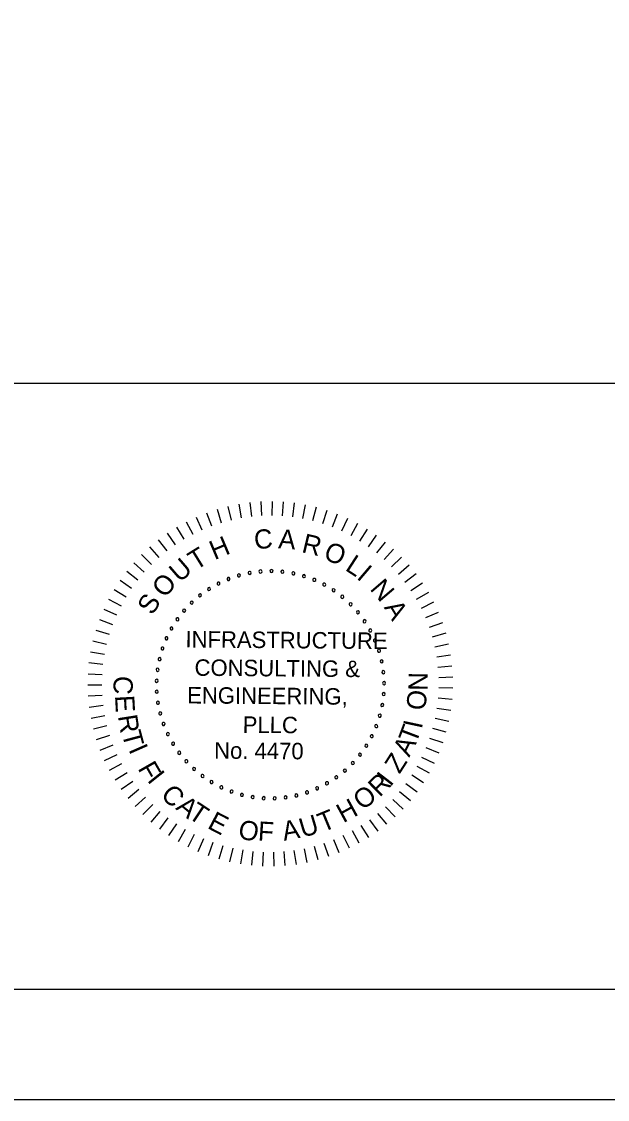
# Model space of a CAD drawing. Extents: x -305 to -161, y -187 to -99.
# Drawn here: x -204.36 to -193.73, y -187.49 to -167.93 of the extents above; entities that cross this region are included whole.
import ezdxf

# ---------------------------------------------------------------- set-up
doc = ezdxf.new("R2010")
doc.units = 0
for name, color, linetype in [('BR_BORDER LINES', 7, 'Continuous'), ('BR_TEXT', 7, 'Continuous'), ('Level 31', 7, 'Continuous')]:
    doc.layers.add(name, color=color, linetype=linetype)

msp = doc.modelspace()

# ---------------------------------------------------------------- linework, layer by layer
at = {"layer": 'BR_BORDER LINES'}
for p, q in [((-214.64, -174.489), (-193.18, -174.489)), ((-297.843, -185.489), (-163.178, -185.489))]:
    msp.add_line(p, q, dxfattribs=at)
at = {"layer": 'BR_TEXT'}
for p, q in [((-200.016, -176.64), (-200.002, -176.894)), ((-199.814, -176.636), (-199.816, -176.89)), ((-200.81, -176.779), (-200.735, -177.023)), ((-200.615, -176.726), (-200.555, -176.974)), ((-200.417, -176.685), (-200.373, -176.936)), ((-200.217, -176.656), (-200.188, -176.909)), ((-199.612, -176.644), (-199.63, -176.898)), ((-199.411, -176.664), (-199.444, -176.917)), ((-199.212, -176.697), (-199.26, -176.947)), ((-199.015, -176.741), (-199.079, -176.988)), ((-198.821, -176.798), (-198.9, -177.04)), ((-201.37, -177.007), (-201.252, -177.233)), ((-201.188, -176.92), (-201.084, -177.153)), ((-201.001, -176.844), (-200.912, -177.082)), ((-198.631, -176.866), (-198.724, -177.103)), ((-198.446, -176.946), (-198.553, -177.177)), ((-201.716, -177.215), (-201.572, -177.425)), ((-201.546, -177.106), (-201.415, -177.324)), ((-198.265, -177.037), (-198.387, -177.261)), ((-198.091, -177.139), (-198.226, -177.355)), ((-201.879, -177.334), (-201.723, -177.535)), ((-197.923, -177.251), (-198.071, -177.458)), ((-197.762, -177.373), (-197.922, -177.571)), ((-202.182, -177.601), (-202.002, -177.781)), ((-202.035, -177.463), (-201.866, -177.654)), ((-197.609, -177.505), (-197.781, -177.693)), ((-202.321, -177.748), (-202.13, -177.917)), ((-197.464, -177.646), (-197.647, -177.823)), ((-197.329, -177.795), (-197.522, -177.961)), ((-202.45, -177.903), (-202.25, -178.06)), ((-197.202, -177.952), (-197.405, -178.106)), ((-202.57, -178.065), (-202.36, -178.21)), ((-197.086, -178.117), (-197.298, -178.258)), ((-202.679, -178.235), (-202.461, -178.366)), ((-196.979, -178.289), (-197.199, -178.417)), ((-202.867, -178.593), (-202.634, -178.696)), ((-202.779, -178.411), (-202.553, -178.529)), ((-196.883, -178.467), (-197.111, -178.581)), ((-202.944, -178.779), (-202.705, -178.869)), ((-196.799, -178.65), (-197.033, -178.75)), ((-203.009, -178.97), (-202.766, -179.045)), ((-196.725, -178.838), (-196.965, -178.924)), ((-203.063, -179.165), (-202.815, -179.225)), ((-196.664, -179.03), (-196.908, -179.101)), ((-203.104, -179.363), (-202.853, -179.407)), ((-196.614, -179.226), (-196.862, -179.282)), ((-203.134, -179.562), (-202.881, -179.592)), ((-196.576, -179.424), (-196.827, -179.465)), ((-203.151, -179.764), (-202.897, -179.777)), ((-196.55, -179.625), (-196.804, -179.65)), ((-203.156, -179.965), (-202.901, -179.964)), ((-196.537, -179.826), (-196.791, -179.836)), ((-203.149, -180.167), (-202.895, -180.15)), ((-196.535, -180.028), (-196.79, -180.022)), ((-203.129, -180.368), (-202.877, -180.335)), ((-196.547, -180.23), (-196.8, -180.208)), ((-203.097, -180.568), (-202.847, -180.52)), ((-196.57, -180.43), (-196.822, -180.393)), ((-203.053, -180.765), (-202.807, -180.701)), ((-196.606, -180.629), (-196.855, -180.577)), ((-202.997, -180.959), (-202.755, -180.881)), ((-196.713, -181.018), (-196.954, -180.936)), ((-196.653, -180.825), (-196.899, -180.758)), ((-202.93, -181.149), (-202.693, -181.056)), ((-196.784, -181.207), (-197.02, -181.111)), ((-202.851, -181.335), (-202.62, -181.228)), ((-196.867, -181.392), (-197.096, -181.281)), ((-202.761, -181.516), (-202.536, -181.395)), ((-196.96, -181.57), (-197.182, -181.446)), ((-202.66, -181.69), (-202.443, -181.556)), ((-202.548, -181.859), (-202.34, -181.711)), ((-197.065, -181.743), (-197.279, -181.605)), ((-202.426, -182.02), (-202.228, -181.86)), ((-197.304, -182.068), (-197.5, -181.905)), ((-197.179, -181.91), (-197.385, -181.759)), ((-202.295, -182.173), (-202.107, -182.002)), ((-197.438, -182.219), (-197.623, -182.045)), ((-202.155, -182.319), (-201.977, -182.136)), ((-202.006, -182.455), (-201.84, -182.262)), ((-197.733, -182.495), (-197.895, -182.3)), ((-197.581, -182.362), (-197.756, -182.176)), ((-201.849, -182.582), (-201.695, -182.379)), ((-201.685, -182.699), (-201.543, -182.487)), ((-197.892, -182.62), (-198.042, -182.414)), ((-201.513, -182.806), (-201.385, -182.586)), ((-201.336, -182.903), (-201.221, -182.675)), ((-198.411, -182.93), (-198.522, -182.701)), ((-198.232, -182.837), (-198.356, -182.615)), ((-198.059, -182.734), (-198.196, -182.519)), ((-201.153, -182.988), (-201.053, -182.754)), ((-200.965, -183.062), (-200.879, -182.822)), ((-200.773, -183.125), (-200.702, -182.88)), ((-198.978, -183.142), (-199.045, -182.896)), ((-198.785, -183.083), (-198.867, -182.842)), ((-198.596, -183.012), (-198.692, -182.777)), ((-200.577, -183.175), (-200.521, -182.927)), ((-200.379, -183.214), (-200.338, -182.962)), ((-200.179, -183.24), (-200.154, -182.987)), ((-199.978, -183.254), (-199.968, -183)), ((-199.776, -183.256), (-199.781, -183.002)), ((-199.574, -183.246), (-199.595, -182.992)), ((-199.373, -183.223), (-199.41, -182.971)), ((-199.174, -183.188), (-199.226, -182.939))]:
    msp.add_line(p, q, dxfattribs=at)
for centre, start, end in [((-200.414, -177.98), 16.1422, 196.1422), ((-200.414, -177.98), 196.1422, 16.1422), ((-200.22, -177.935), 10.6038, 190.6038), ((-200.22, -177.935), 190.6038, 10.6038), ((-200.023, -177.908), 5.0653, 185.0653), ((-200.023, -177.908), 185.0653, 5.0653), ((-199.824, -177.9), 359.5268, 179.5268), ((-199.824, -177.9), 179.5268, 359.5268), ((-199.625, -177.912), 353.9884, 173.9884), ((-199.625, -177.912), 173.9884, 353.9884), ((-199.428, -177.943), 168.4499, 348.4499), ((-199.428, -177.943), 348.4499, 168.4499), ((-199.235, -177.992), 162.9114, 342.9114), ((-199.235, -177.992), 342.9114, 162.9114), ((-200.957, -178.226), 32.7576, 212.7576), ((-200.785, -178.127), 27.2191, 207.2191), ((-200.785, -178.127), 207.2191, 27.2191), ((-200.603, -178.045), 21.6807, 201.6807), ((-200.603, -178.045), 201.6807, 21.6807), ((-199.047, -178.06), 157.373, 337.373), ((-199.047, -178.06), 337.373, 157.373), ((-198.867, -178.146), 151.8345, 331.8345), ((-198.867, -178.146), 331.8345, 151.8345), ((-201.12, -178.341), 38.2961, 218.2961), ((-201.12, -178.341), 218.2961, 38.2961), ((-200.957, -178.226), 212.7576, 32.7576), ((-198.697, -178.249), 146.2961, 326.2961), ((-198.697, -178.249), 326.2961, 146.2961), ((-198.537, -178.368), 140.7576, 320.7576), ((-198.537, -178.368), 320.7576, 140.7576), ((-201.408, -178.617), 49.373, 229.373), ((-201.408, -178.617), 229.373, 49.373), ((-201.27, -178.472), 43.8345, 223.8345), ((-201.27, -178.472), 223.8345, 43.8345), ((-198.389, -178.502), 135.2191, 315.2191), ((-198.389, -178.502), 315.2191, 135.2191), ((-201.53, -178.774), 54.9114, 234.9114), ((-201.53, -178.774), 234.9114, 54.9114), ((-198.255, -178.649), 129.6807, 309.6807), ((-198.255, -178.649), 309.6807, 129.6807), ((-198.135, -178.809), 124.1422, 304.1422), ((-198.135, -178.809), 304.1422, 124.1422), ((-201.637, -178.942), 60.4499, 240.4499), ((-201.637, -178.942), 240.4499, 60.4499), ((-198.032, -178.979), 118.6038, 298.6038), ((-198.032, -178.979), 298.6038, 118.6038), ((-201.727, -179.12), 65.9884, 245.9884), ((-201.727, -179.12), 245.9884, 65.9884), ((-197.945, -179.159), 113.0653, 293.0653), ((-197.945, -179.159), 293.0653, 113.0653), ((-201.8, -179.305), 71.5268, 251.5268), ((-201.8, -179.305), 251.5268, 71.5268), ((-197.876, -179.346), 107.5268, 287.5268), ((-197.876, -179.346), 287.5268, 107.5268), ((-201.854, -179.497), 77.0653, 257.0653), ((-201.854, -179.497), 257.0653, 77.0653), ((-197.826, -179.538), 101.9884, 281.9884), ((-197.826, -179.538), 281.9884, 101.9884), ((-201.89, -179.693), 82.6038, 262.6038), ((-201.89, -179.693), 262.6038, 82.6038), ((-197.795, -179.735), 96.4499, 276.4499), ((-197.795, -179.735), 276.4499, 96.4499), ((-201.906, -179.892), 88.1422, 268.1422), ((-201.906, -179.892), 268.1422, 88.1422), ((-197.782, -179.934), 90.9114, 270.9114), ((-197.782, -179.934), 270.9114, 90.9114), ((-201.904, -180.091), 93.6807, 273.6807), ((-201.904, -180.091), 273.6807, 93.6807), ((-197.789, -180.133), 85.373, 265.373), ((-197.789, -180.133), 265.373, 85.373), ((-201.882, -180.289), 99.2191, 279.2191), ((-201.882, -180.289), 279.2191, 99.2191), ((-197.815, -180.331), 79.8345, 259.8345), ((-197.815, -180.331), 259.8345, 79.8345), ((-201.841, -180.484), 104.7576, 284.7576), ((-201.841, -180.484), 284.7576, 104.7576), ((-197.86, -180.525), 74.2961, 254.2961), ((-197.86, -180.525), 254.2961, 74.2961), ((-201.781, -180.675), 110.2961, 290.2961), ((-201.781, -180.675), 290.2961, 110.2961), ((-197.924, -180.714), 68.7576, 248.7576), ((-197.924, -180.714), 248.7576, 68.7576), ((-201.703, -180.858), 115.8345, 295.8345), ((-201.703, -180.858), 295.8345, 115.8345), ((-198.005, -180.896), 63.2191, 243.2191), ((-198.005, -180.896), 243.2191, 63.2191), ((-201.608, -181.033), 121.373, 301.373), ((-201.608, -181.033), 301.373, 121.373), ((-198.104, -181.069), 57.6807, 237.6807), ((-198.104, -181.069), 237.6807, 57.6807), ((-201.497, -181.199), 126.9114, 306.9114), ((-201.497, -181.199), 306.9114, 126.9114), ((-201.37, -181.352), 132.4499, 312.4499), ((-201.37, -181.352), 312.4499, 132.4499), ((-198.219, -181.232), 52.1422, 232.1422), ((-198.219, -181.232), 232.1422, 52.1422), ((-201.228, -181.493), 137.9884, 317.9884), ((-201.228, -181.493), 317.9884, 137.9884), ((-198.493, -181.521), 41.0653, 221.0653), ((-198.493, -181.521), 221.0653, 41.0653), ((-198.349, -181.383), 46.6038, 226.6038), ((-198.349, -181.383), 226.6038, 46.6038), ((-201.074, -181.619), 143.5268, 323.5268), ((-201.074, -181.619), 323.5268, 143.5268), ((-200.909, -181.73), 149.0653, 329.0653), ((-200.909, -181.73), 329.0653, 149.0653), ((-198.817, -181.752), 29.9884, 209.9884), ((-198.649, -181.644), 35.5268, 215.5268), ((-198.649, -181.644), 215.5268, 35.5268), ((-200.733, -181.825), 154.6038, 334.6038), ((-200.733, -181.825), 334.6038, 154.6038), ((-200.549, -181.902), 160.1422, 340.1422), ((-200.549, -181.902), 340.1422, 160.1422), ((-199.18, -181.916), 18.9114, 198.9114), ((-199.18, -181.916), 198.9114, 18.9114), ((-198.995, -181.842), 24.4499, 204.4499), ((-198.995, -181.842), 204.4499, 24.4499), ((-198.817, -181.752), 209.9884, 29.9884), ((-200.359, -181.961), 165.6807, 345.6807), ((-200.359, -181.961), 345.6807, 165.6807), ((-200.164, -182.001), 171.2191, 351.2191), ((-200.164, -182.001), 351.2191, 171.2191), ((-199.965, -182.022), 176.7576, 356.7576), ((-199.965, -182.022), 356.7576, 176.7576), ((-199.766, -182.024), 2.2961, 182.2961), ((-199.766, -182.024), 182.2961, 2.2961), ((-199.568, -182.007), 7.8345, 187.8345), ((-199.568, -182.007), 187.8345, 7.8345), ((-199.372, -181.971), 13.373, 193.373), ((-199.372, -181.971), 193.373, 13.373)]:
    msp.add_arc(centre, 0.028, start, end, dxfattribs=at)
at = {"layer": 'Level 31'}
msp.add_lwpolyline([(-305.176, -187.489), (-161.176, -187.489), (-161.176, -99.489), (-305.176, -99.489)], close=True, dxfattribs=at)

# ---------------------------------------------------------------- texts
at = {"layer": 'BR_TEXT'}
for s, height, rotation, p in [('C', 0.349, 4.7281, (-200.126, -177.506)), ('A', 0.349, 355.6981, (-199.708, -177.486)), ('R', 0.349, 346.6681, (-199.291, -177.554)), ('H', 0.349, 22.7882, (-200.857, -177.704)), ('O', 0.349, 337.638, (-198.9, -177.673)), ('T', 0.349, 31.8182, (-201.196, -177.894)), ('L', 0.349, 327.108, (-198.504, -177.875)), ('U', 0.349, 40.8482, (-201.49, -178.119)), ('I', 0.349, 319.578, (-198.294, -178.026)), ('O', 0.349, 49.8782, (-201.757, -178.403)), ('N', 0.349, 310.548, (-198.051, -178.23)), ('S', 0.349, 58.9083, (-201.979, -178.715)), ('A', 0.349, 301.5179, (-197.791, -178.559)), ('INFRASTRUCTURE', 0.29909, 359.5268, (-201.385, -179.286)), ('CONSULTING &', 0.29909, 359.5268, (-201.22, -179.8)), ('N', 0.349, 89.2085, (-196.993, -180.074)), ('C', 0.349, 267.025, (-202.679, -179.795)), ('ENGINEERING,', 0.29909, 359.5268, (-201.354, -180.302)), ('O', 0.349, 83.2085, (-197.038, -180.44)), ('E', 0.349, 273.025, (-202.662, -180.161)), ('R', 0.349, 279.025, (-202.61, -180.531)), ('PLLC', 0.2991, 359.5268, (-200.347, -180.836)), ('T', 0.349, 69.3954, (-197.203, -181.047)), ('I', 0.349, 77.9093, (-197.1, -180.777)), ('T', 0.349, 285.025, (-202.541, -180.846)), ('I', 0.349, 293.7713, (-202.422, -181.138)), ('No. 4470', 0.2991, 359.5268, (-200.865, -181.304)), ('A', 0.349, 63.3954, (-197.326, -181.288)), ('Z', 0.349, 57.3954, (-197.501, -181.594)), ('F', 0.349, 299.7713, (-202.257, -181.482)), ('I', 0.349, 308.5268, (-202.089, -181.698)), ('R', 0.349, 44.5268, (-197.863, -182.014)), ('I', 0.349, 52.3339, (-197.665, -181.825)), ('C', 0.349, 314.5268, (-201.851, -181.978)), ('O', 0.349, 38.5268, (-198.169, -182.254)), ('A', 0.349, 320.5268, (-201.575, -182.213)), ('T', 0.349, 326.5268, (-201.357, -182.366)), ('H', 0.349, 28.5268, (-198.522, -182.478)), ('E', 0.349, 332.5268, (-201.003, -182.558)), ('T', 0.349, 22.5268, (-198.894, -182.645)), ('O', 0.349, 350.5268, (-200.442, -182.753)), ('F', 0.349, 356.5268, (-200.076, -182.79)), ('A', 0.349, 10.5268, (-199.597, -182.796)), ('U', 0.349, 16.5268, (-199.261, -182.742))]:
    msp.add_text(s, height=height, rotation=rotation, dxfattribs=at).set_placement(p)

doc.saveas('drawing.dxf')
